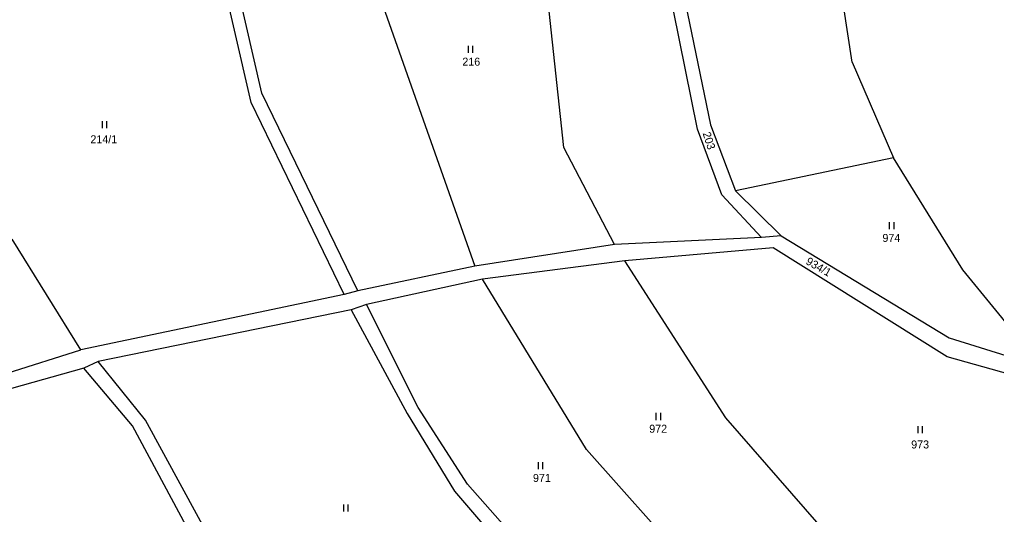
# Model space of a CAD drawing. Extents: x -670359 to -668019, y -978807 to -976674.
# Drawn here: x -669783.1 to -669575.5, y -977570.9 to -977465.8 of the extents above; entities that cross this region are included whole.
import ezdxf

# ---------------------------------------------------------------- set-up
doc = ezdxf.new("R2010")
doc.units = 0
for name, color, linetype in [('Hranice parcel', 7, 'Continuous'), ('Parcelní čísla', 7, 'Continuous'), ('Značky kultur', 7, 'Continuous')]:
    doc.layers.add(name, color=color, linetype=linetype)

msp = doc.modelspace()

# ---------------------------------------------------------------- linework, layer by layer
at = {"layer": 'Hranice parcel'}
for points in [[(-669731.56, -977481.43), (-669743.84, -977428.05)], [(-669667.44, -977492.96), (-669673.67, -977434.98)], [(-669733.87, -977483.37), (-669744.27, -977438.16)], [(-669638.99, -977489.03), (-669647.94, -977444.89)], [(-669645.15, -977444.88), (-669636.28, -977488.14)], [(-669606.12, -977474.85), (-669609.96, -977449.78)], [(-669705.83, -977462.98), (-669686.33, -977518.16)], [(-669606.12, -977474.85), (-669597.37, -977495.18)], [(-669711.18, -977523.43), (-669731.56, -977481.43)], [(-669714.13, -977524.16), (-669733.87, -977483.37)], [(-669633.88, -977502.99), (-669638.99, -977489.03)], [(-669636.28, -977488.14), (-669630.92, -977502.17)], [(-669656.69, -977513.59), (-669667.44, -977492.96)], [(-669597.37, -977495.18), (-669630.92, -977502.17)], [(-669582.61, -977518.98), (-669597.37, -977495.18)], [(-669625.43, -977512.05), (-669633.88, -977502.99)], [(-669630.92, -977502.17), (-669621.27, -977511.7)], [(-669621.27, -977511.7), (-669625.43, -977512.05)], [(-669621.27, -977511.7), (-669585.57, -977533.39)], [(-669770.05, -977535.92), (-669784.65, -977512.44)], [(-669656.69, -977513.59), (-669686.33, -977518.16)], [(-669625.43, -977512.05), (-669656.69, -977513.59)], [(-669622.94, -977514.27), (-669654.43, -977517.01)], [(-669585.95, -977537.46), (-669622.94, -977514.27)], [(-669686.33, -977518.16), (-669711.18, -977523.43)], [(-669654.43, -977517.01), (-669684.72, -977520.95)], [(-669632.98, -977550.37), (-669654.43, -977517.01)], [(-669565.78, -977539.58), (-669582.61, -977518.98)], [(-669684.72, -977520.95), (-669709.32, -977526.29)], [(-669662.61, -977557.1), (-669684.72, -977520.95)], [(-669714.13, -977524.16), (-669770.05, -977535.92)], [(-669711.18, -977523.43), (-669714.13, -977524.16)], [(-669709.32, -977526.29), (-669712.59, -977527.43)], [(-669698.41, -977548.2), (-669709.32, -977526.29)], [(-669712.59, -977527.43), (-669766.36, -977538.46)], [(-669712.59, -977527.43), (-669700.72, -977549.5)], [(-669585.57, -977533.39), (-669565.78, -977539.58)], [(-669785.7, -977540.89), (-669770.05, -977535.92)], [(-669766.36, -977538.46), (-669769.39, -977539.84)], [(-669756.29, -977550.87), (-669766.36, -977538.46)], [(-669544.06, -977549.2), (-669585.95, -977537.46)], [(-669769.39, -977539.84), (-669784.8, -977544.16)], [(-669759.08, -977552.08), (-669769.39, -977539.84)], [(-669687.92, -977564.52), (-669698.41, -977548.2)], [(-669741.19, -977578.75), (-669756.29, -977550.87)], [(-669700.72, -977549.5), (-669690.63, -977565.98)], [(-669613.14, -977573.11), (-669632.98, -977550.37)], [(-669744.06, -977580.04), (-669759.08, -977552.08)], [(-669641.45, -977580.95), (-669662.61, -977557.1)], [(-669690.63, -977565.98), (-669673.98, -977585.38)], [(-669671.35, -977583.28), (-669687.92, -977564.52)]]:
    msp.add_lwpolyline(points, dxfattribs=at)
at = {"layer": 'Značky kultur'}
for p, q in [((-669687.74, -977471.37), (-669687.74, -977472.87)), ((-669686.74, -977472.87), (-669686.74, -977471.37)), ((-669765.52, -977487.38), (-669765.52, -977488.88)), ((-669764.52, -977488.88), (-669764.52, -977487.38)), ((-669598.26, -977508.82), (-669598.26, -977510.32)), ((-669597.26, -977510.32), (-669597.26, -977508.82)), ((-669647.84, -977549.36), (-669647.84, -977550.86)), ((-669646.84, -977550.86), (-669646.84, -977549.36)), ((-669592.18, -977552.17), (-669592.18, -977553.67)), ((-669591.18, -977553.67), (-669591.18, -977552.17)), ((-669672.87, -977559.82), (-669672.87, -977561.32)), ((-669671.87, -977561.32), (-669671.87, -977559.82)), ((-669714.23, -977568.79), (-669714.23, -977570.29)), ((-669713.23, -977570.29), (-669713.23, -977568.79))]:
    msp.add_line(p, q, dxfattribs=at)

# ---------------------------------------------------------------- texts
at = {"layer": 'Parcelní čísla'}
for s, p in [('216', (-669688.99, -977475.57)), ('214/1', (-669768.02, -977492.06)), ('974', (-669599.72, -977513.02)), ('972', (-669649.27, -977553.56)), ('973', (-669593.61, -977556.9)), ('971', (-669673.98, -977564.02))]:
    msp.add_text(s, height=1.7, dxfattribs=at).set_placement(p)
for s, rotation, p in [('203', 287.6502, (-669637.94, -977489.94)), ('934/1', 330.1076, (-669616.15, -977517.62))]:
    msp.add_text(s, height=1.7, rotation=rotation, dxfattribs=at).set_placement(p)

doc.saveas('drawing.dxf')
